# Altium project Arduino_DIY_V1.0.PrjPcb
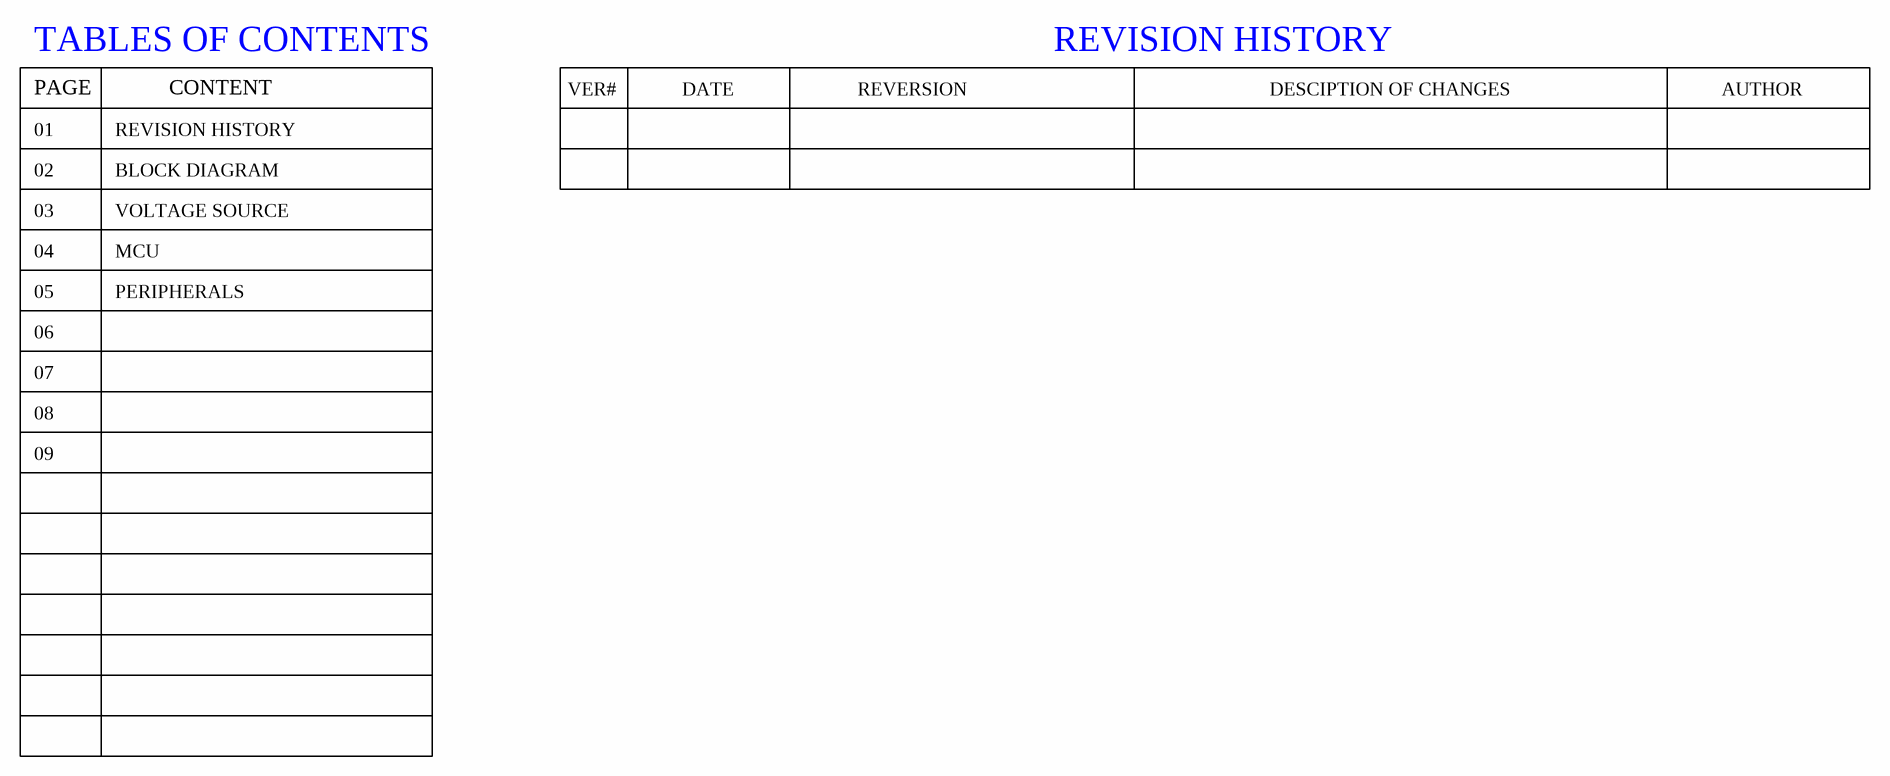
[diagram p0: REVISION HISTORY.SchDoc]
5 sheets, 121 parts. Net scope: flat (ports and power ports of the same name join across sheets).
Board file: Arduino_DIY_V1.0.PcbDoc
Sheets:
  REVISION HISTORY.SchDoc
  BLOCK DIAGRAM.SchDoc
  VOLTAGE SOURCE.SchDoc
  MCU.SchDoc
  Peripheral.SchDoc

## Sheet REVISION HISTORY.SchDoc: REVISION HISTORY
size A3; Author: NGUYEN QUANG MINH; SheetNumber: 1; SheetTotal: 5; ProjectTitle: Arduino_DIY_V1.0

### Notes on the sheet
- TABLES OF CONTENTS
- PAGE
- CONTENT
- VER#
- DATE
- REVERSION
- REVISION HISTORY
- DESCIPTION OF CHANGES
- AUTHOR
- 01
- 02
- 03
- BLOCK DIAGRAM
- VOLTAGE SOURCE
- 04
- MCU
- 05
- 06
- PERIPHERALS
- 07
- 08
- 09

## Sheet BLOCK DIAGRAM.SchDoc: BLOCK DIAGRAM
size A3; Author: NGUYEN QUANG MINH; SheetNumber: 2; SheetTotal: 5; ProjectTitle: Arduino_DIY_V1.0
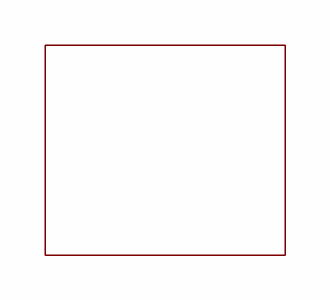
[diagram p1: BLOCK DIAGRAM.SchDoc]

## Sheet VOLTAGE SOURCE.SchDoc: VOLTAGE SOURCE
size A3; Author: NGUUYEN QUANG MINH; Organization: My Company; Address1: Address Line 1; Address2: Address Line 2; Address3: Address Line 3; Address4: Address Line 4; SheetNumber: 3; SheetTotal: 5; ProjectTitle: Arduino_DIY_V1.0
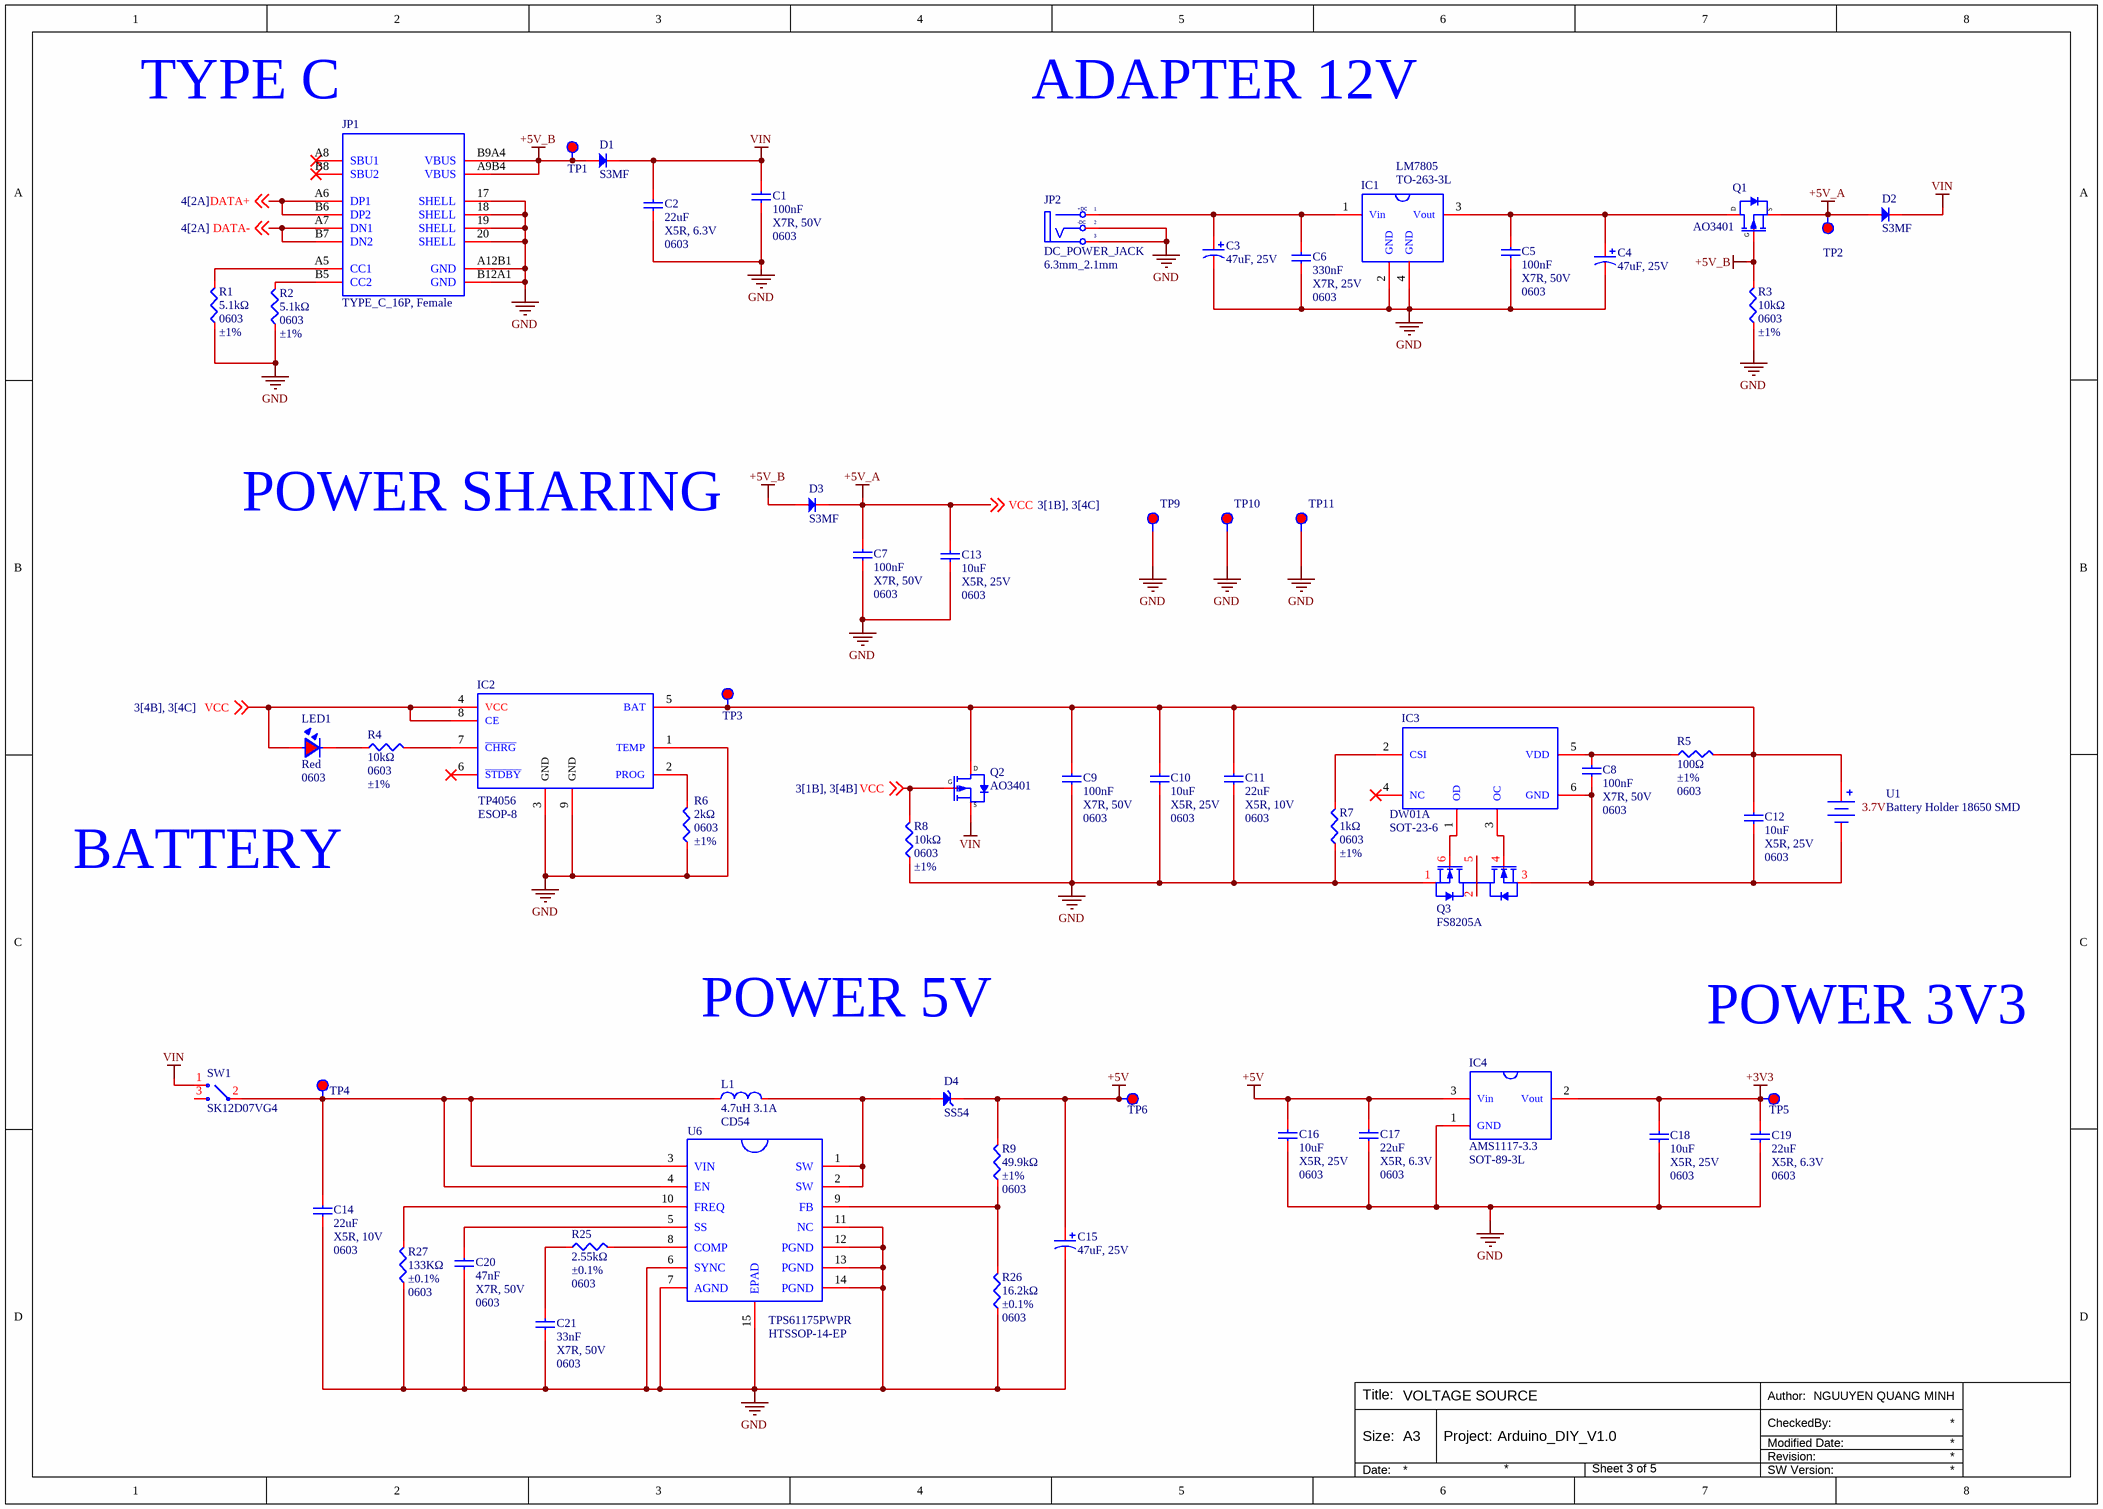
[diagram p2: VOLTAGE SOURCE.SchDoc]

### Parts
C1  100nF  Temperature Coefficient: X7R, 50V  Package: 0603  [C0603]
C2  22uF  Temperature Coefficient: X5R, 6.3V  Package: 0603  [C0603]
C3  47uF, 25V  [CAP_ALU_C]
C4  47uF, 25V  [CAP_ALU_C]
C5  100nF  Temperature Coefficient: X7R, 50V  Package: 0603  [C0603]
C6  330nF  Temperature Coefficient: X7R, 25V  Package: 0603  [C0603]
C7  100nF  Temperature Coefficient: X7R, 50V  Package: 0603  [C0603]
C8  100nF  Temperature Coefficient: X7R, 50V  Package: 0603  [C0603]
C9  100nF  Temperature Coefficient: X7R, 50V  Package: 0603  [C0603]
C10  10uF  Temperature Coefficient: X5R, 25V  Package: 0603  [C0603]
C11  22uF  Temperature Coefficient: X5R, 10V  Package: 0603  [C0603]
C12  10uF  Temperature Coefficient: X5R, 25V  Package: 0603  [C0603]
C13  10uF  Temperature Coefficient: X5R, 25V  Package: 0603  [C0603]
C14  22uF  Temperature Coefficient: X5R, 10V  Package: 0603  [C0603]
C15  47uF, 25V  [CAP_ALU_C]
C16  10uF  Temperature Coefficient: X5R, 25V  Package: 0603  [C0603]
C17  22uF  Temperature Coefficient: X5R, 6.3V  Package: 0603  [C0603]
C18  10uF  Temperature Coefficient: X5R, 25V  Package: 0603  [C0603]
C19  22uF  Temperature Coefficient: X5R, 6.3V  Package: 0603  [C0603]
C20  47nF  Temperature Coefficient: X7R, 50V  Package: 0603  [C0603]
C21  33nF  Temperature Coefficient: X7R, 50V  Package: 0603  [C0603]
D1  S3MF  [D_SMAF_L3.5-W2.6-LS4.7-RD]
D2  S3MF  [D_SMAF_L3.5-W2.6-LS4.7-RD]
D3  S3MF  [D_SMAF_L3.5-W2.6-LS4.7-RD]
D4  SS54  [SMC]
IC1  LM7805  [TO-263-3L]
IC2  TP4056  [ESOP-8]
IC3  DW01A  [SOT-23-6]
IC4  AMS1117-3.3  [SOT-89-3L]
JP1  TYPE_C_16P, Female  [TYPE_C_16P]
JP2  DC_POWER_JACK  Reference: 6.3mm_2.1mm  [DC_POWER_JACK_6.3mm_2.1mm]
L1  4.7uH 3.1A  [CD54]
LED1  Red  Package: 0603  [LED0603_RED]
Q1  AO3401  [TF_SOT_23_3]
Q2  AO3401  [TF_SOT_23_3]
Q3  FS8205A  [TF_SOT23-6]
R1  5.1kΩ  Package: 0603  Tolerance: ±1%  [R0603]
R2  5.1kΩ  Package: 0603  Tolerance: ±1%  [R0603]
R3  10kΩ  Package: 0603  Tolerance: ±1%  [R0603]
R4  10kΩ  Package: 0603  Tolerance: ±1%  [R0603]
R5  100Ω  Tolerance: ±1%  Package: 0603  [R0603]
R6  2kΩ  Package: 0603  Tolerance: ±1%  [R0603]
R7  1kΩ  Package: 0603  Tolerance: ±1%  [R0603]
R8  10kΩ  Package: 0603  Tolerance: ±1%  [R0603]
R9  49.9kΩ  Tolerance: ±1%  Package: 0603  [R0603]
R25  2.55kΩ  Tolerance: ±0.1%  Package: 0603  [R0603]
R26  16.2kΩ  Tolerance: ±0.1%  Package: 0603  [R0603]
R27  133KΩ  Tolerance: ±0.1%  Package: 0603  [R0603]
SW1  SK12D07VG4  [SK12D07VG4]
TP1  Test Point  [TEST_POINT]  (value not drawn)  (no BOM)
TP2  Test Point  [TEST_POINT]  (value not drawn)  (no BOM)
TP3  Test Point  [TEST_POINT]  (value not drawn)  (no BOM)
TP4  Test Point  [TEST_POINT]  (value not drawn)  (no BOM)
TP5  Test Point  [TEST_POINT]  (value not drawn)  (no BOM)
TP6  Test Point  [TEST_POINT]  (value not drawn)  (no BOM)
TP9  Test Point  [TEST_POINT]  (value not drawn)  (no BOM)
TP10  Test Point  [TEST_POINT]  (value not drawn)  (no BOM)
TP11  Test Point  [TEST_POINT]  (value not drawn)  (no BOM)
U1  Battery Holder 18650 SMD  [PIN_18650_1S_HOLDER_SMD]
U6  TPS61175PWPR  [HTSSOP-14-EP]

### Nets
+3V3: C18.2 C19.2 IC4.2(Vout) TP5.1
+5V: C15.1 C16.2 C17.2 D4.1 IC4.3(Vin) R9.2 TP6.1
+5V_A: C7.2 C13.2 D2.2 D3.1 IC2.4(VCC) IC2.8(CE) LED1.1 Q1.2(S) Q2.1(G) R8.2 TP2.1 ; off-sheet VCC  [also labelled VCC]
+5V_B: D1.2 D3.2 JP1.A9B4(VBUS) JP1.B9A4(VBUS) Q1.1(G) R3.2 TP1.1
GND: C1.1 C2.1 C3.2 C4.2 C5.1 C6.1 C7.1 C9.1 C10.1 C11.1 C13.1 C14.1 C15.2 C16.1 C17.1 C18.1 C19.1 C20.1 C21.1 IC1.2(GND) IC1.4(GND) IC2.1(TEMP) IC2.3(GND) IC2.9(GND) IC4.1(GND) JP1.17(SHELL) JP1.18(SHELL) JP1.19(SHELL) JP1.20(SHELL) JP1.A12B1(GND) JP1.B12A1(GND) JP2.2(TN) JP2.3(S) Q3.1(S1) R1.1 R2.1 R3.1 R6.1 R7.1 R8.1 R26.1 R27.1 TP9.1 TP10.1 TP11.1 U6.6(SYNC) U6.7(AGND) U6.11(NC) U6.12(PGND) U6.13(PGND) U6.14(PGND) U6.15(EPAD)
VIN: C1.2 C2.2 D1.1 D2.1 Q2.2(S) SW1.1
DATA+: JP1.A6(DP1) JP1.B6(DP2) ; off-sheet DATA+
DATA-: JP1.A7(DN1) JP1.B7(DN2) ; off-sheet DATA-
NetC3_1: C3.1 C6.2 IC1.1(Vin) JP2.1(T)
NetC4_1: C4.1 C5.2 IC1.3(Vout) Q1.3(D)
NetC8_1: C8.1 C12.1 IC3.6(GND) Q3.3(S2) U1.2
NetC8_2: C8.2 IC3.5(VDD) R5.1
NetC9_2: C9.2 C10.2 C11.2 C12.2 IC2.5(BAT) Q2.3(D) R5.2 TP3.1 U1.1
NetC14_2: C14.2 L1.1 SW1.2 TP4.1 U6.3(VIN) U6.4(EN)
NetC20_2: C20.2 U6.5(SS)
NetC21_2: C21.2 R25.1
NetD4_2: D4.2 L1.2 U6.1(SW) U6.2(SW)
NetIC2_2: IC2.2(PROG) R6.2
NetIC2_7: IC2.7(~{CHRG}) R4.2
NetIC3_1: IC3.1(OD) Q3.6(G1)
NetIC3_2: IC3.2(CSI) R7.2
NetIC3_3: IC3.3(OC) Q3.4(G2)
NetJP1_A5: JP1.A5(CC1) R1.2
NetJP1_B5: JP1.B5(CC2) R2.2
NetLED1_2: LED1.2 R4.1
NetQ3_2: Q3.2(D1/D2) Q3.5(D1/D2)
NetR9_1: R9.1 R26.2 U6.9(FB)
NetR25_2: R25.2 U6.8(COMP)
NetR27_2: R27.2 U6.10(FREQ)

Not connected (* = marked no-connect by the designer): IC2 6(~{STDBY})*; IC3 4(NC)*; JP1 A8(SBU1)* B8(SBU2)*; SW1 3

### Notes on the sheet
- TYPE C
- ADAPTER 12V
- POWER SHARING
- BATTERY
- POWER 5V
- POWER 3V3

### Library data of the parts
C1 C5 C7-C9 = C0603_MLCC_100nF_X7R_50V: 50V 100nF X7R ±10% 0603 Multilayer Ceramic Capacitors MLCC - SMD/SMT ROHS; Manufacturer: YAGEO; Mfr. Part: CC0603KRX7R9BB104
C2 C17 C19 = C0603_MLCC_22uF_X5R_6.3V: 6.3V 22uF X5R ±20% 0603 Multilayer Ceramic Capacitors MLCC - SMD/SMT ROHS; Manufacturer: YAGEO; Mfr. Part: CC0603MRX5R5BB226
C3 C4 C15 = C_ALU_47uF_25V_C: 25V ±20% 47uF SMD,D5xL6.1mm Hybrid Aluminum Electrolytic Capacitors ROHS; Manufacturer: PANASONIC; Mfr. Part: EEHZK1E470R
C6 = C0603_MLCC_330nF_X7R_25V: 25V 330nF X7R ±10% 0603 Multilayer Ceramic Capacitors MLCC - SMD/SMT ROHS; Manufacturer: YAGEO; Mfr. Part: CC0603KRX7R8BB334
C10 C12 C13 C16 C18 = C0603_MLCC_10uF_X5R_25V: 25V 10uF X5R ±20% 0603 Multilayer Ceramic Capacitors MLCC - SMD/SMT ROHS; Manufacturer: YAGEO; Mfr. Part: CC0603MRX5R8BB106
C11 C14 = C0603_MLCC_22uF_X5R_10V: 10V 22uF X5R ±20% 0603 Multilayer Ceramic Capacitors MLCC - SMD/SMT ROHS; Manufacturer: Samsung Electro-Mechanics; Mfr. Part: CL10A226MP8NUNE
C20 = C0603_MLCC_47nF_X7R_50V: 50V 47nF X7R ±10% 0603 Multilayer Ceramic Capacitors MLCC - SMD/SMT ROHS; Manufacturer: YAGEO; Mfr. Part: CC0603KRX7R9BB473
C21 = C0603_MLCC_33nF_X7R_50V: 50V 33nF X7R ±10% 0603 Multilayer Ceramic Capacitors MLCC - SMD/SMT ROHS; Manufacturer: YAGEO; Mfr. Part: CC0603KRX7R9BB333
D1-D3 = S3MF: 3A Independent Type 1.1V@3A 1kV SMAF Diodes - General Purpose ROHS; Manufacturer: Shandong Jingdao Microelectronics
D4 = SS54: 40V Independent 550mV@5A 5A SMC Schottky Diodes ROHS; Manufacturer: TWGMC
IC1 = LM7805_TO-263-3L: 62dB@(120Hz) 1A Fixed 4.8V~5.2V Positive 35V TO-263-3L Voltage Regulators - Linear, Low Drop Out (LDO) Regulators ROHS; Manufacturer: HANSCHIP semiconductor; Mfr. Part: LM7805SRG; Number of Outputs: 1
IC2 = TP4056_ESOP-8: 4V~6V Lithium-ion/Polymer 1 ESOP-8 Battery Management ROHS; Manufacturer: TPOWER; Key Attributes: 1A Lithium Battery Charger; Number of Cells: 1; Charging Saturation Voltage: 4.2V
IC3 = DW01A: 1.5V~8V Lithium-ion/Polymer 1 SOT-23-6 Battery Management ROHS; Manufacturer: YONGYUTAI; Key Attributes: Lithium battery protection circuit; Number of Cells: 1; Charging Saturation Voltage: 4.3V
IC4 = AMS1117-3.3_SOT-89-3L: 1A Fixed 3.3V Positive 15V SOT-89-3L Voltage Regulators - Linear, Low Drop Out (LDO) Regulators ROHS; Manufacturer: HXY MOSFET; Voltage Dropout: 12mV@(1A); Number of Outputs: 1; Voltage - Supply: 16V
JP1 = TYPE_C_16P: 3A USB 3.1 1 Surface Mount, Right Angle 16P Female -40℃~+85℃ Type-C SMD USB Connectors ROHS; Manufacturer: SHOU HAN; Mfr. Part: TYPE-C-3.1-16PIN; Protocol Standard: USB 3.1
JP2 = DC_POWER_JACK_6.3mm_2.1mm: Right Angle DC Power Jack -40℃~+85℃ 2.1mm 6.3mm 3A 500V Through Hole DC Power Connectors ROHS; Manufacturer: Lian Xin Technology; Mfr. Part: XDJK-0051-025
L1 = CD54_4.7uH_3.1A: 3.1A 4.7uH ±20% SMD,5.8x5.2mm Power Inductors ROHS; Manufacturer: Ceaiya; Manufacture Part Number: CD54-4R7M
LED1 = LED0603_Red: 20mA 230mcd Water Clear -40℃~+85℃ 630nm Red 120° 75mW 1.95V 0603 LED Indication - Discrete ROHS; Manufacturer: Kingbright; Mfr. Part: APT1608SURCK; Key Attributes: 1.6 x 0.8 mm SMD Chip LED Lamp
Q1 Q2 = AO3401: 30V 4.2A 42mΩ@10V,4A 1.4W 800mV@250uA 1 Piece P-Channel SOT-23 MOSFETs ROHS; Manufacturer: ElecSuper
Q3 = FS8205A: 20V 25mΩ@2.5V,3A 1.5W 500mV SOT-23-6 MOSFETs ROHS; Manufacturer: TECH PUBLIC
R1 R2 = R0603_5.1kΩ_±1%: 100mW Thick Film Resistor 75V ±100ppm/℃ ±1% 5.1kΩ 0603 Chip Resistor - Surface Mount ROHS; Manufacturer: YAGEO; Mfr. Part: RC0603FR-075K1L
R3 R4 R8 = R0603_10kΩ_±1%: 100mW Thick Film Resistor 75V ±100ppm/℃ ±1% 10kΩ 0603 Chip Resistor - Surface Mount ROHS; Manufacturer: YAGEO; Mfr. Part: RC0603FR-0710KL
R5 = R0603_100Ω_±1%: 100mW Thick Film Resistor 75V ±100ppm/℃ ±1% 100Ω 0603 Chip Resistor - Surface Mount ROHS; Manufacturer: YAGEO; Mfr. Part: RC0603FR-13100RL
R6 = R0603_2kΩ_±1%: 100mW Thick Film Resistor 75V ±100ppm/℃ ±1% 2kΩ 0603 Chip Resistor - Surface Mount ROHS; Manufacturer: YAGEO; Mfr. Part: RC0603FR-072KL
R7 = R0603_1kΩ_±1%: 100mW Thick Film Resistor 75V ±100ppm/℃ ±1% 1kΩ 0603 Chip Resistor - Surface Mount ROHS; Manufacturer: YAGEO; Mfr. Part: RC0603FR-071KL
R9 = R0603_49.9KΩ_±1%: 100mW Thick Film Resistor 75V ±100ppm/℃ ±1% 49.9kΩ 0603 Chip Resistor - Surface Mount ROHS; Manufacturer: YAGEO; Mfr. Part: RC0603FR-0749K9L
R25 = R0603_2.55KΩ_±0.1%: 100mW Thin Film Resistor 75V ±25ppm/℃ ±0.1% 2.55kΩ 0603 Chip Resistor - Surface Mount ROHS; Manufacturer: YAGEO; Mfr. Part: RT0603BRD072K55L
R26 = R0603_16.2KΩ_±0.1%: 100mW Thin Film Resistor 75V ±50ppm/℃ ±0.1% 16.2kΩ 0603 Chip Resistor - Surface Mount ROHS; Manufacturer: YAGEO; Mfr. Part: RT0603BRE0716K2L
R27 = R0603_133KΩ_±0.1%: 100mW Thin Film Resistor 75V ±50ppm/℃ ±0.1% 133kΩ 0603 Chip Resistor - Surface Mount ROHS; Manufacturer: YAGEO; Mfr. Part: RT0603BRE07133KL
SW1 = SK12D07VG4: 500mA SPDT 50V 5千次 Plugin Slide Switches ROHS; Manufacturer: SHOU HAN
TP1-TP6 TP9-TP11 = TEST_POINT
U1 = PIN_18650_1S_HOLDER_SMD: Battery Holder -10℃~+100℃ Gold Phosphor Bronze Button And Strip Battery Connector ROHS; Manufacturer: MYOUNG; Mfr. Part: BH-18650-B5BA008; Battery Type: 18650
U6 = TPS61175PWPR: Boost Adjustable 2.9V~38V 2.9V~18V 3A HTSSOP-14-EP DC-DC Converters ROHS; Manufacturer: TI; Frequency - Switching: 2.2MHz; Number of Outputs: 1

## Sheet MCU.SchDoc: MCU
size A3; Author: NGUYEN QUANG MINH; SheetNumber: 4; SheetTotal: 5; ProjectTitle: Arduino_DIY_V1.0
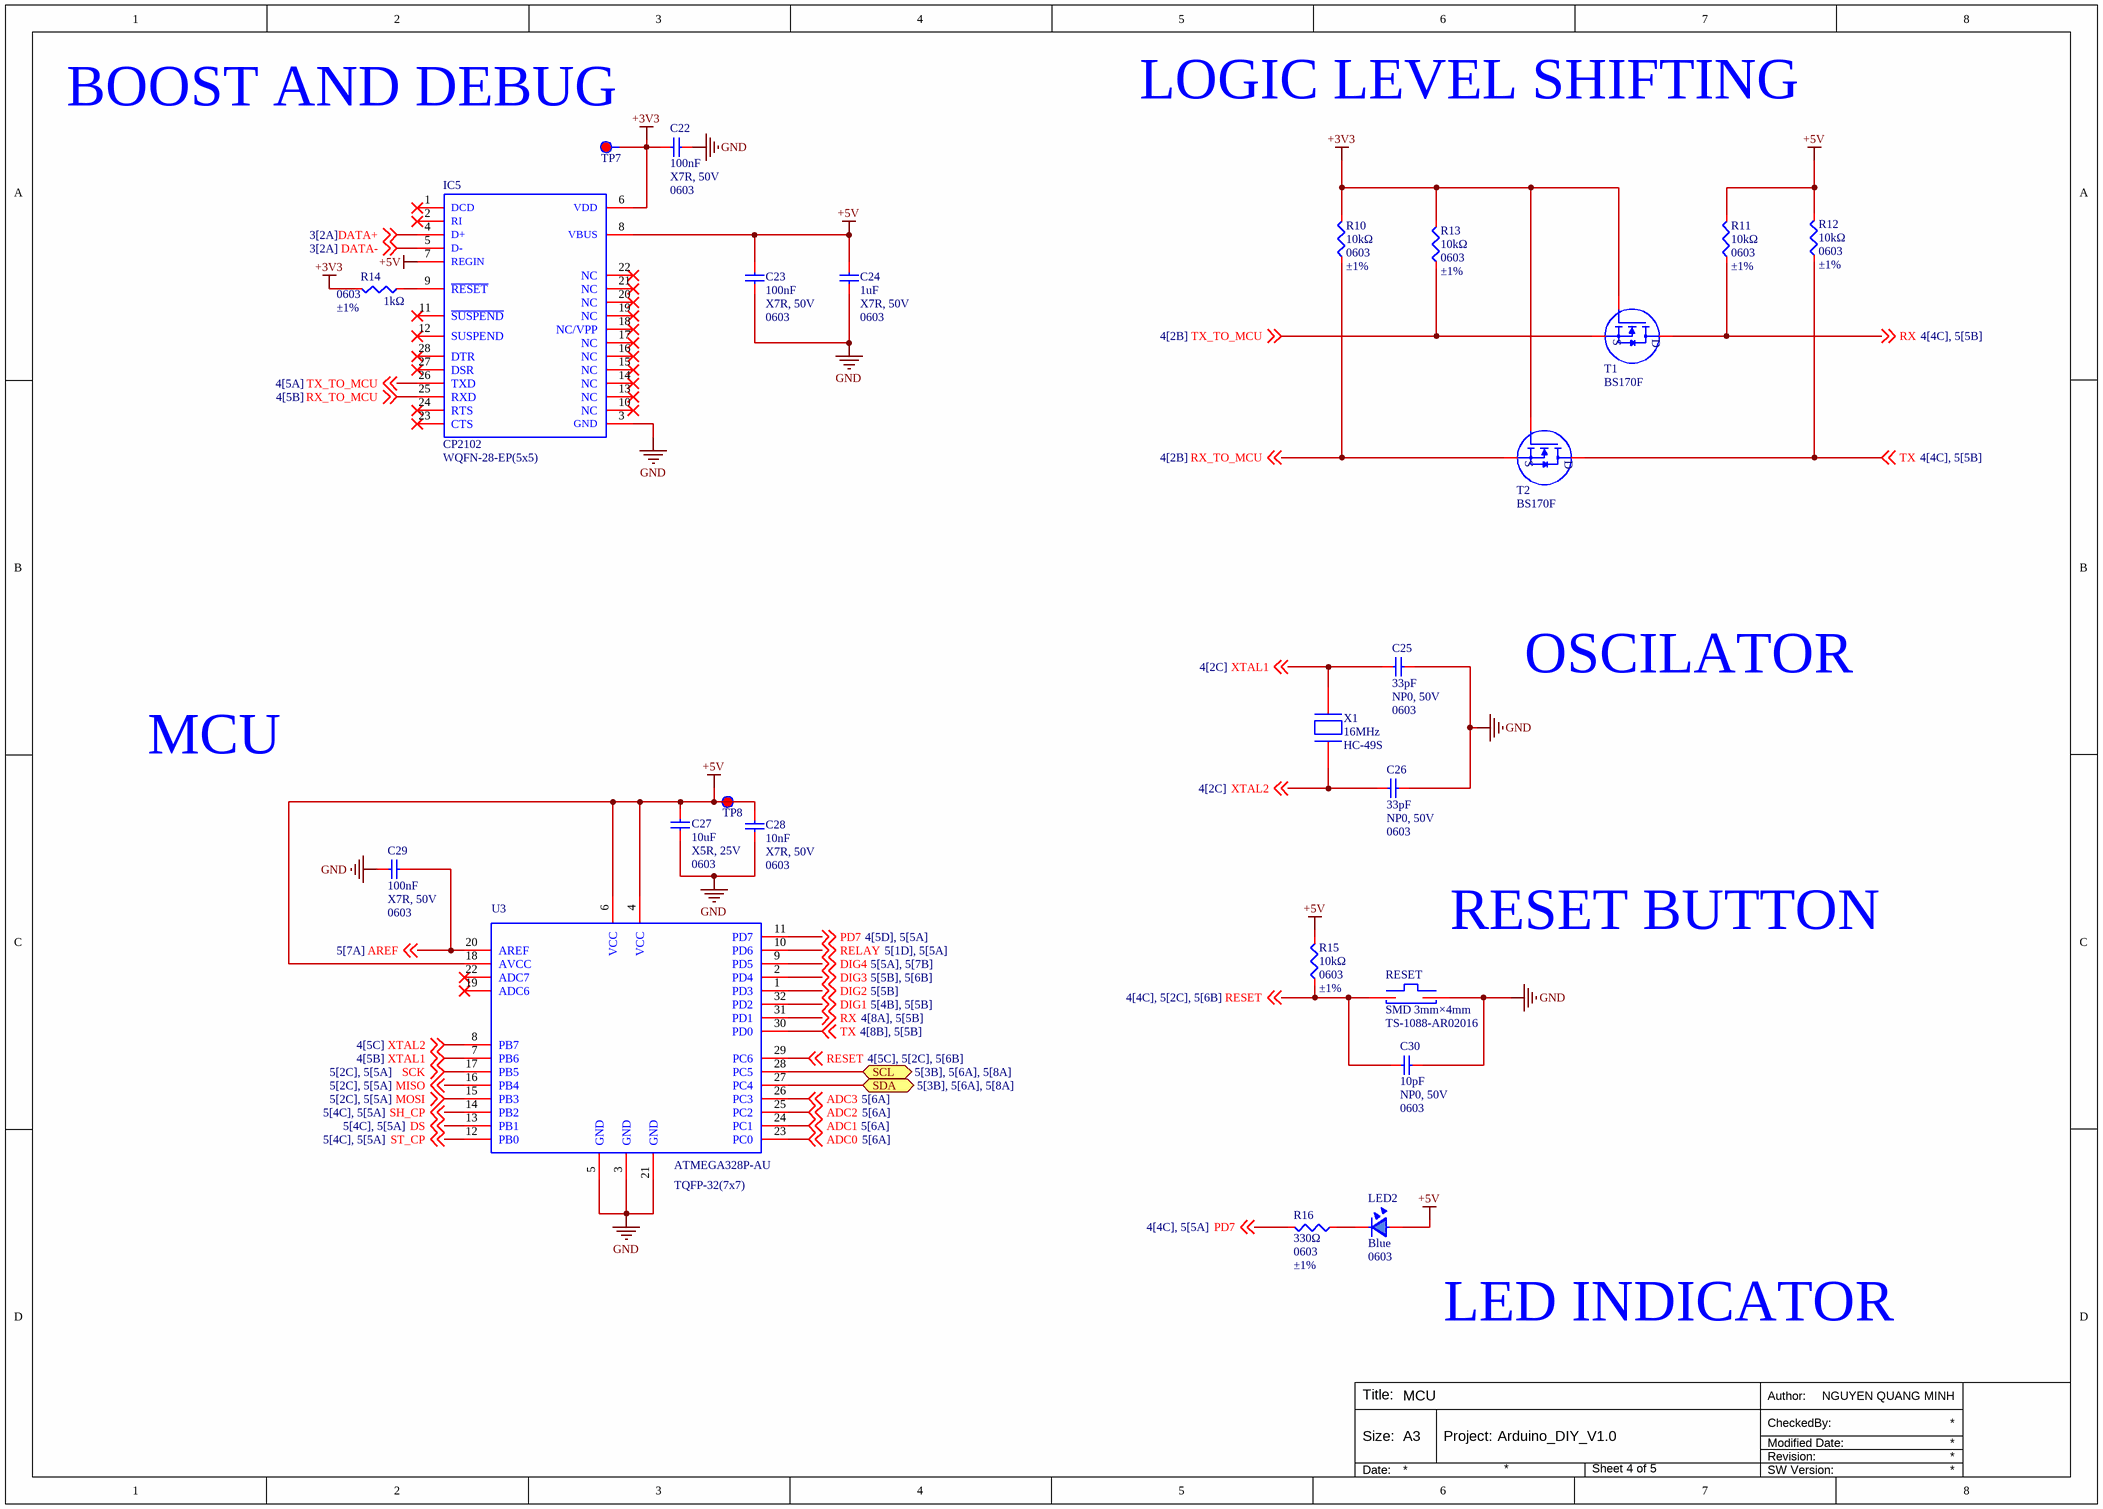
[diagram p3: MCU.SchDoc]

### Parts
C22  100nF  Temperature Coefficient: X7R, 50V  Package: 0603  [C0603]
C23  100nF  Temperature Coefficient: X7R, 50V  Package: 0603  [C0603]
C24  1uF  Temperature Coefficient: X7R, 50V  Package: 0603  [C0603]
C25  33pF  Temperature Coefficient: NP0, 50V  Package: 0603  [C0603]
C26  33pF  Temperature Coefficient: NP0, 50V  Package: 0603  [C0603]
C27  10uF  Temperature Coefficient: X5R, 25V  Package: 0603  [C0603]
C28  10nF  Temperature Coefficient: X7R, 50V  Package: 0603  [C0603]
C29  100nF  Temperature Coefficient: X7R, 50V  Package: 0603  [C0603]
C30  10pF  Temperature Coefficient: NP0, 50V  Package: 0603  [C0603]
IC5  CP2102  [WQFN-28-EP(5x5)]
LED2  Blue  Package: 0603  [LED0603_BLUE]
R10  10kΩ  Package: 0603  Tolerance: ±1%  [R0603]
R11  10kΩ  Package: 0603  Tolerance: ±1%  [R0603]
R12  10kΩ  Package: 0603  Tolerance: ±1%  [R0603]
R13  10kΩ  Package: 0603  Tolerance: ±1%  [R0603]
R14  1kΩ  Package: 0603  Tolerance: ±1%  [R0603]
R15  10kΩ  Package: 0603  Tolerance: ±1%  [R0603]
R16  330Ω  Package: 0603  Tolerance: ±1%  [R0603]
RESET  SMD 3mm×4mm  Mfr. Part: TS-1088-AR02016  [ROUND_BUTTON_SMD 3*4mm]
T1  BS170F  [SOT-23]
T2  BS170F  [SOT-23]
TP7  Test Point  [TEST_POINT]  (value not drawn)  (no BOM)
TP8  Test Point  [TEST_POINT]  (value not drawn)  (no BOM)
U3  ATMEGA328P-AU  Package: TQFP-32(7x7)  [TQFP-32 (7x7)]
X1  16MHz  [HC-49S]

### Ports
SCL (bidir, see 5[3B], 5[6A], 5[8A]), SDA (bidir, see 5[3B], 5[6A], 5[8A])

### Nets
+3V3: C22.2 IC5.6(VDD) R10.2 R13.2 R14.2 T1.1(G) T2.1(G) TP7.1
+5V: C23.2 C24.2 C27.2 C28.2 IC5.7(REGIN) IC5.8(VBUS) LED2.1 R11.2 R12.2 R15.2 TP8.1 U3.4(VCC) U3.6(VCC) U3.18(AVCC)
GND: C22.1 C23.1 C24.1 C25.2 C26.2 C27.1 C28.1 C29.1 C30.2 IC5.3(GND) RESET.2 U3.3(GND) U3.5(GND) U3.21(GND)
ADC0: U3.23(PC0) ; off-sheet ADC0
ADC1: U3.24(PC1) ; off-sheet ADC1
ADC2: U3.25(PC2) ; off-sheet ADC2
ADC3: U3.26(PC3) ; off-sheet ADC3
AREF: C29.2 U3.20(AREF) ; off-sheet AREF
DATA+: IC5.4(D+) ; off-sheet DATA+
DATA-: IC5.5(D-) ; off-sheet DATA-
DIG1: U3.32(PD2) ; off-sheet DIG1
DIG2: U3.1(PD3) ; off-sheet DIG2
DIG3: U3.2(PD4) ; off-sheet DIG3
DIG4: U3.9(PD5) ; off-sheet DIG4
DS: U3.13(PB1) ; off-sheet DS
MISO: U3.16(PB4) ; off-sheet MISO
MOSI: U3.15(PB3) ; off-sheet MOSI
PD7: R16.1 U3.11(PD7) ; off-sheet PD7
RELAY: U3.10(PD6) ; off-sheet RELAY
RESET: C30.1 R15.1 RESET.1 U3.29(PC6) ; off-sheet RESET
RX: R11.1 T1.3(D) U3.31(PD1) ; off-sheet RX
RX_TO_MCU: IC5.25(RXD) R10.1 T2.2(S) ; off-sheet RX_TO_MCU
SCK: U3.17(PB5) ; off-sheet SCK
SH_CP: U3.14(PB2) ; off-sheet SH_CP
ST_CP: U3.12(PB0) ; off-sheet ST_CP
TX: R12.1 T2.3(D) U3.30(PD0) ; off-sheet TX
TX_TO_MCU: IC5.26(TXD) R13.1 T1.2(S) ; off-sheet TX_TO_MCU
XTAL1: C25.1 U3.7(PB6) X1.2 ; off-sheet XTAL1
XTAL2: C26.1 U3.8(PB7) X1.1 ; off-sheet XTAL2
NetH2_1: U3.28(PC5) ; port SCL
NetH2_2: U3.27(PC4) ; port SDA
NetIC5_9: IC5.9(~{RESET}) R14.1
NetLED2_2: LED2.2 R16.2

Not connected (* = marked no-connect by the designer): IC5 1(DCD)* 2(RI)* 10(NC)* 11(~{SUSPEND})* 12(SUSPEND)* 13(NC)* 14(NC)* 15(NC)* 16(NC)* 17(NC)* 18(NC/VPP)* 19(NC)* 20(NC)* 21(NC)* 22(NC)* 23(CTS)* 24(RTS)* 27(DSR)* 28(DTR)*; U3 19(ADC6)* 22(ADC7)*

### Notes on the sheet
- LOGIC LEVEL SHIFTING
- BOOST AND DEBUG
- OSCILATOR
- MCU
- RESET BUTTON
- LED INDICATOR

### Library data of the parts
C22 C23 C29 = C0603_MLCC_100nF_X7R_50V: as C1 on sheet VOLTAGE SOURCE
C24 = C0603_MLCC_1uF_X7R_50V: 50V 1uF X7R ±10% 0603 Multilayer Ceramic Capacitors MLCC - SMD/SMT ROHS; Manufacturer: YAGEO; Mfr. Part: CC0603KRX7R9BB105
C25 C26 = C0603_MLCC_33pF_NP0_50V: 50V 33pF NP0 ±5% 0603 Multilayer Ceramic Capacitors MLCC - SMD/SMT ROHS; Manufacturer: YAGEO; Mfr. Part: CC0603JRNPO9BN330
C27 = C0603_MLCC_10uF_X5R_25V: as C10 on sheet VOLTAGE SOURCE
C28 = C0603_MLCC_10nF_X7R_50V: 50V 10nF X7R ±10% 0603 Multilayer Ceramic Capacitors MLCC - SMD/SMT ROHS; Manufacturer: YAGEO; Mfr. Part: CC0603KRX7R9BB103
C30 = C0603_MLCC_10pF_NP0_50V: 50V 10pF NP0 ±5% 0603 Multilayer Ceramic Capacitors MLCC - SMD/SMT ROHS; Manufacturer: YAGEO; Mfr. Part: CC0603JRNPO9BN100
IC5 = CP2102: 12Mbps Transceiver WQFN-28-EP(5x5) USB Converters ROHS; Manufacturer: SILICON LABS; Mfr. Part: CP2102-GMR; Key Attributes: Single-Chip USB to UART Bridge; Voltage - Supply: 3V~3.6V
LED2 = LED0603_Blue: 2mA 24mcd Water Clear -40℃~+85℃ 470nm Blue 130° 120mW 2.65V 0603 LED Indication - Discrete ROHS; Manufacturer: Kingbright; Mfr. Part: APT1608LVBC/D; Key Attributes: 1.6 x 0.8 mm SMD Chip LED Lamp
R10-R13 R15 = R0603_10kΩ_±1%: as R3 on sheet VOLTAGE SOURCE
R14 = R0603_1kΩ_±1%: as R7 on sheet VOLTAGE SOURCE
R16 = R0603_330Ω_±1%: 100mW Thick Film Resistor 75V ±100ppm/℃ ±1% 330Ω 0603 Chip Resistor - Surface Mount ROHS; Manufacturer: YAGEO; Mfr. Part: RC0603FR-07330RL
RESET = SW_BUTTON_SMD_3mm×4mm: Without Bracket 50mA 4mm 100,000 Cycles 12V 1.6N 3mm 2mm Round Button Surface Mount,Vertical SPST SMD Tactile Switches ROHS; Manufacturer: XUNPU
T1 T2 = BS170F: 90V 150uA 5Ω@10V 330mW 3V@1mA 1 N-Channel SOT-23 MOSFETs ROHS; Manufacturer: DIODES
TP7 TP8 = TEST_POINT
U3 = ATMEGA328P-AU: AVR 20MHz TQFP-32(7x7) Microcontrollers (MCU/MPU/SOC) ROHS; Manufacturer: MICROCHIP; Key Attributes: 8-bit Microcontroller with In-System Programmable Flash; ADC (Bit): 10bit; Number of I/O: 23; Program Memory Type: FLASH; EEPROM: 1KB; Program Storage Size: 32KB; Voltage - Supply: 1.8V~5.5V
X1 = Crystal_16Mhz_HC49S: 16MHz Through Hole Crystal Oscillator 20pF ±20ppm ±30ppm HC-49S Crystals ROHS; Manufacturer: YXC Crystal Oscillators; Mfr. Part: X49SD16MSD2SC

## Sheet Peripheral.SchDoc
size A3; SheetNumber: 5; SheetTotal: 5
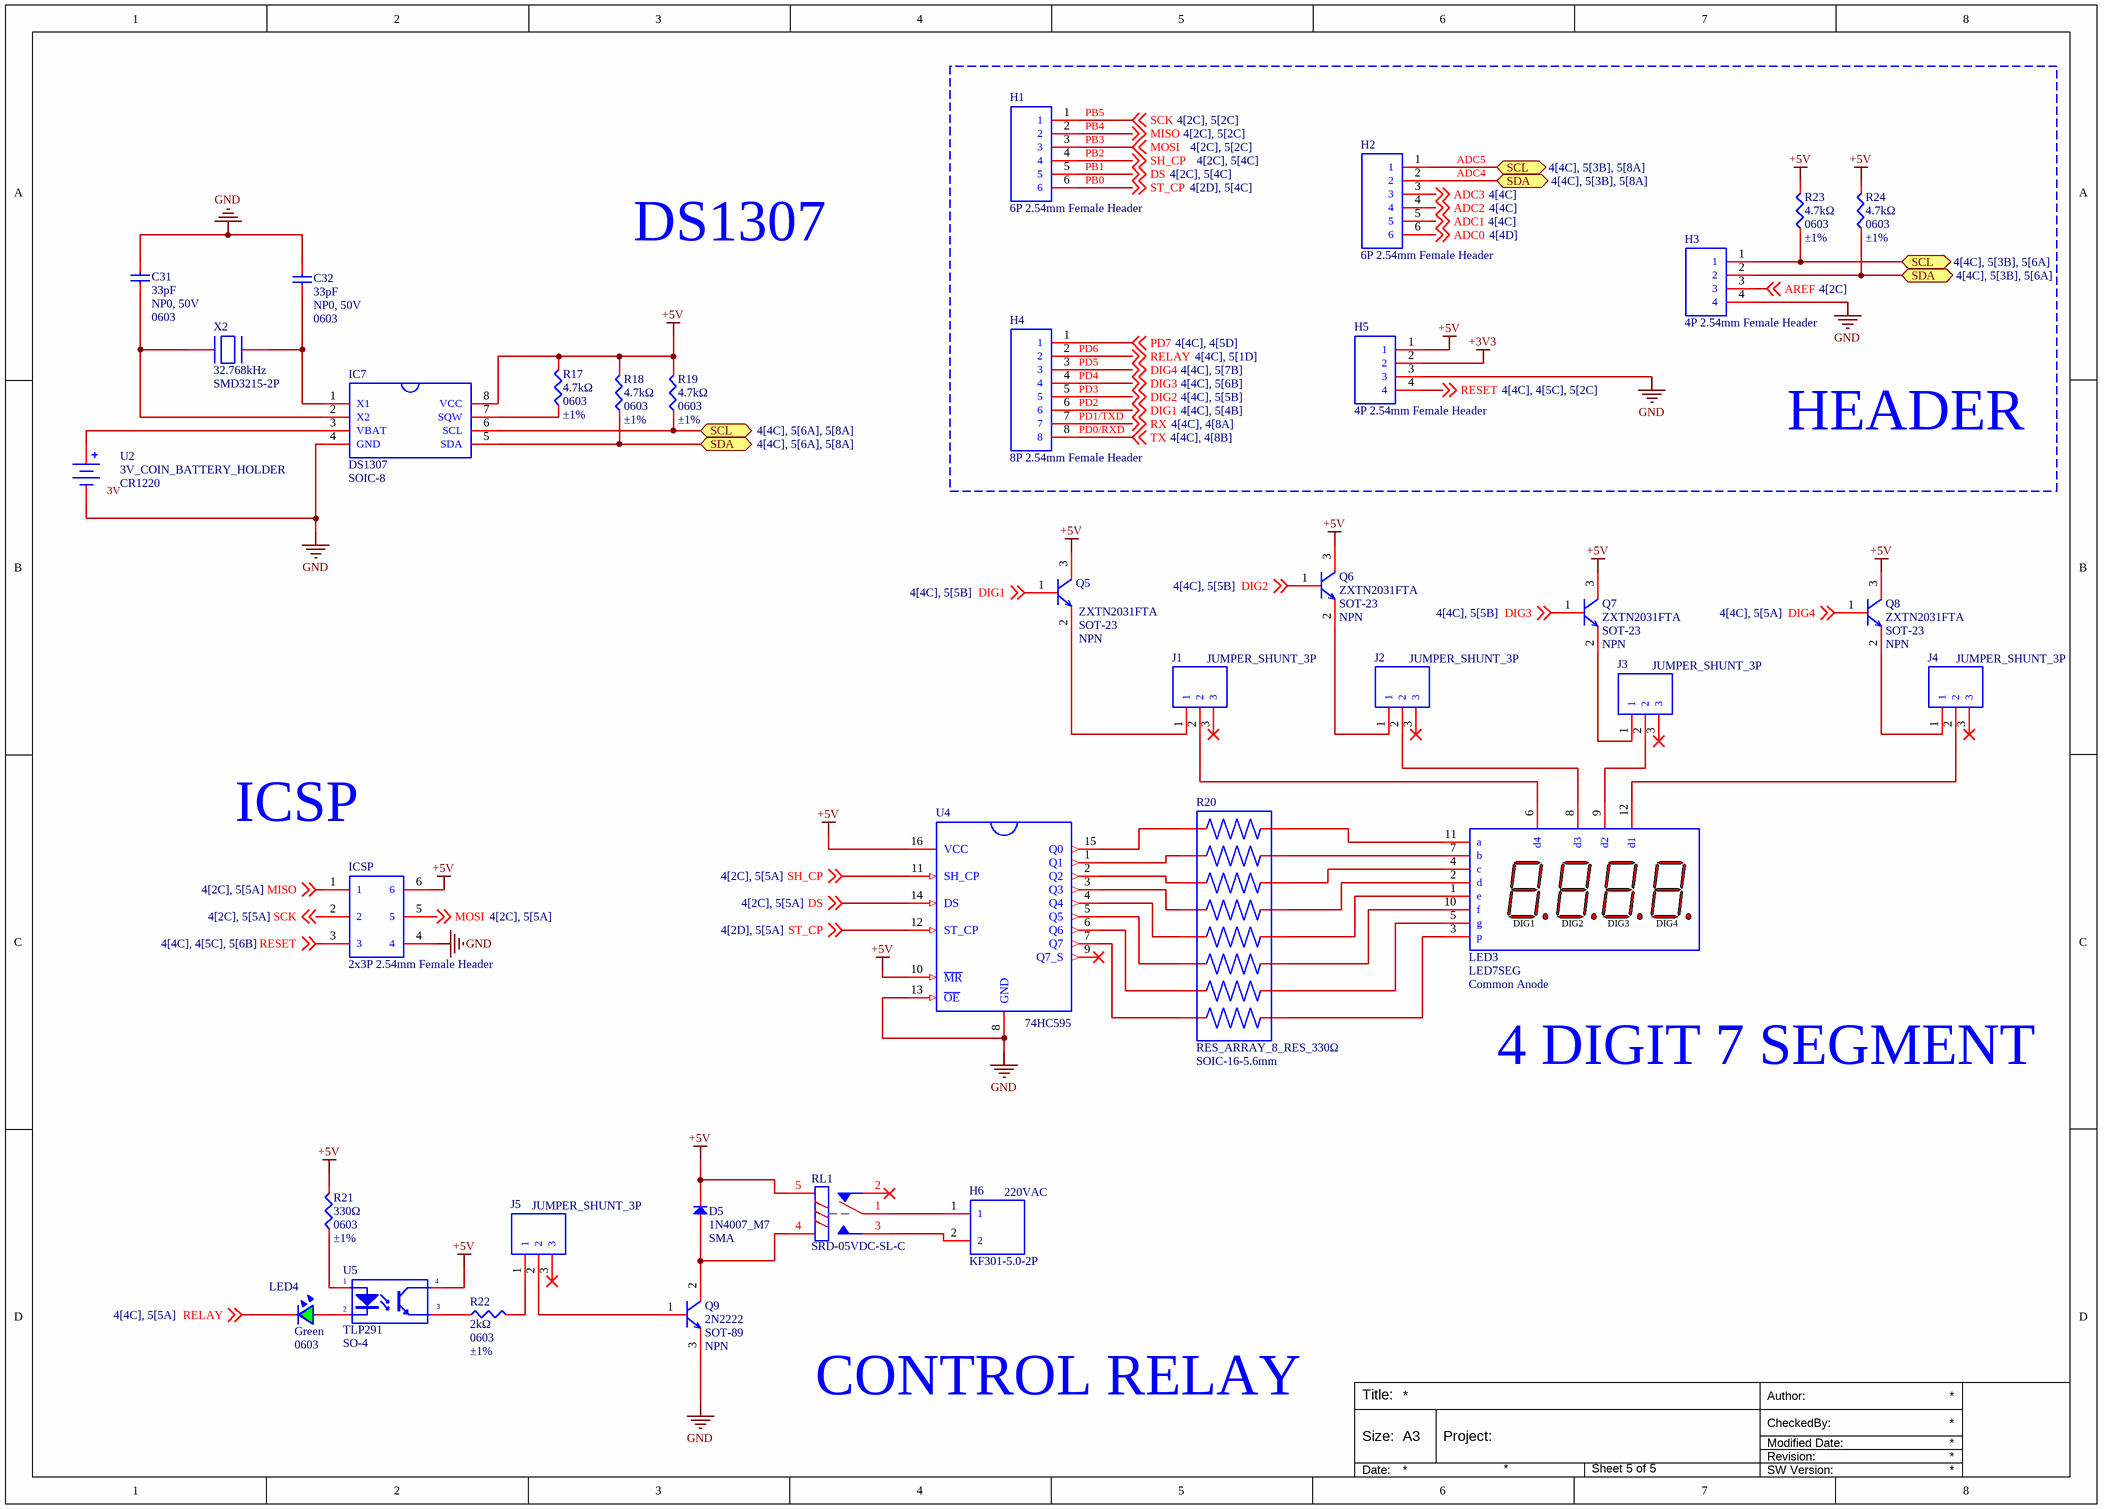
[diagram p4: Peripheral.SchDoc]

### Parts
C31  33pF  Temperature Coefficient: NP0, 50V  Package: 0603  [C0603]
C32  33pF  Temperature Coefficient: NP0, 50V  Package: 0603  [C0603]
D5  1N4007_M7  Package: SMA  [SMA(DO-214AC)]
H1  6P 2.54mm Female Header  [6P, 2,54mm, FEMALE HEADER]
H2  6P 2.54mm Female Header  [6P, 2,54mm, FEMALE HEADER]
H3  4P 2.54mm Female Header  [4P, 2,54mm, FEMALE HEADER]
H4  8P 2.54mm Female Header  [8P, 2,54mm, FEMALE HEADER]
H5  4P 2.54mm Female Header  [4P, 2,54mm, FEMALE HEADER]
H6  KF301-5.0-2P  CONFIGURE: 220VAC  [CONN-TH_P5.00_KF301-5.0-2P]
IC7  DS1307  [SOIC-8]
ICSP  2x3P 2.54mm Female Header  [2x3P, 2.54mm, Female Header]
J1  JUMPER_SHUNT_3P  [JUMPER_SHUNT_3P]
J2  JUMPER_SHUNT_3P  [JUMPER_SHUNT_3P]
J3  JUMPER_SHUNT_3P  [JUMPER_SHUNT_3P]
J4  JUMPER_SHUNT_3P  [JUMPER_SHUNT_3P]
J5  JUMPER_SHUNT_3P  [JUMPER_SHUNT_3P]
LED3  LED7SEG  LED Polarity: Common Anode  [LED7SEG_4]
LED4  Green  Package: 0603  [LED0603_GREEN]
Q5  ZXTN2031FTA  Type: NPN  [SOT-23]
Q6  ZXTN2031FTA  Type: NPN  [SOT-23]
Q7  ZXTN2031FTA  Type: NPN  [SOT-23]
Q8  ZXTN2031FTA  Type: NPN  [SOT-23]
Q9  2N2222  Package: SOT-89  Type: NPN  [SOT-89-3L]
R17  4.7kΩ  Package: 0603  Tolerance: ±1%  [R0603]
R18  4.7kΩ  Package: 0603  Tolerance: ±1%  [R0603]
R19  4.7kΩ  Package: 0603  Tolerance: ±1%  [R0603]
R20  RES_ARRAY_8_RES_330Ω  [SOIC-16-5.6mm]
R21  330Ω  Package: 0603  Tolerance: ±1%  [R0603]
R22  2kΩ  Package: 0603  Tolerance: ±1%  [R0603]
R23  4.7kΩ  Package: 0603  Tolerance: ±1%  [R0603]
R24  4.7kΩ  Package: 0603  Tolerance: ±1%  [R0603]
RL1  SRD-05VDC-SL-C  [Through Hole,15.6x19.2mm]
U2  3V_COIN_BATTERY_HOLDER  Battery Type: CR1220  [3V_COIN_BATERRY_HOLDER_CR1220]
U4  74HC595  [TSSOP16]
U5  TLP291  [SO-4]
X2  32.768kHz  [SMD3215-2P]

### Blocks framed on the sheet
HEADER: H1-H5 R23 R24

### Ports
SCL (bidir, see 4[4C], 5[3B], 5[6A]), SCL (bidir, see 4[4C], 5[3B], 5[8A]), SCL (bidir, see 4[4C], 5[6A], 5[8A]), SDA (bidir, see 4[4C], 5[3B], 5[6A]), SDA (bidir, see 4[4C], 5[3B], 5[8A]), SDA (bidir, see 4[4C], 5[6A], 5[8A])

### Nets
+3V3: H5.2
+5V: D5.1 H5.1 IC7.8(VCC) ICSP.6 Q5.3(C) Q6.3(C) Q7.3(C) Q8.3(C) R17.2 R18.2 R19.2 R21.2 R23.2 R24.2 RL1.5 U4.10(~{MR}) U4.16(VCC) U5.4(C)
GND: C31.2 C32.2 H3.4 H5.3 IC7.4(GND) ICSP.4 Q9.3(E) U2.2 U4.8(GND) U4.13(~{OE})
ADC0: H2.6 ; off-sheet ADC0
ADC1: H2.5 ; off-sheet ADC1
ADC2: H2.4 ; off-sheet ADC2
ADC3: H2.3 ; off-sheet ADC3
AREF: H3.3 ; off-sheet AREF
DIG1: H4.6 Q5.1(B) ; off-sheet DIG1
DIG2: H4.5 Q6.1(B) ; off-sheet DIG2
DIG3: H4.4 Q7.1(B) ; off-sheet DIG3
DIG4: H4.3 Q8.1(B) ; off-sheet DIG4
DS: H1.5 U4.14(DS) ; off-sheet DS
MISO: H1.2 ICSP.1 ; off-sheet MISO
MOSI: H1.3 ICSP.5 ; off-sheet MOSI
PD7: H4.1 ; off-sheet PD7
RELAY: H4.2 LED4.2 ; off-sheet RELAY
RESET: H5.4 ICSP.3 ; off-sheet RESET
RX: H4.7 ; off-sheet RX
SCK: H1.1 ICSP.2 ; off-sheet SCK
SH_CP: H1.4 U4.11(SH_CP) ; off-sheet SH_CP
ST_CP: H1.6 U4.12(ST_CP) ; off-sheet ST_CP
TX: H4.8 ; off-sheet TX
NetC31_1: C31.1 IC7.2(X2) X2.2
NetC32_1: C32.1 IC7.1(X1) X2.1
NetD5_2: D5.2 Q9.2(C) RL1.4
NetH2_1: H2.1 H3.1 IC7.6(SCL) R19.1 R23.1 ; port SCL
NetH2_2: H2.2 H3.2 IC7.5(SDA) R18.1 R24.1 ; port SDA
NetH6_1: H6.1 RL1.1
NetH6_2: H6.2 RL1.3
NetIC7_3: IC7.3(VBAT) U2.1
NetIC7_7: IC7.7(SQW) R17.1
NetJ1_1: J1.1 Q5.2(E)
NetJ1_2: J1.2 LED3.6(d4)
NetJ2_1: J2.1 Q6.2(E)
NetJ2_2: J2.2 LED3.8(d3)
NetJ3_1: J3.1 Q7.2(E)
NetJ3_2: J3.2 LED3.9(d2)
NetJ4_1: J4.1 Q8.2(E)
NetJ4_2: J4.2 LED3.12(d1)
NetJ5_1: J5.1 R22.2
NetJ5_2: J5.2 Q9.1(B)
NetLED3_1: LED3.1(e) R20.12
NetLED3_2: LED3.2(d) R20.13
NetLED3_3: LED3.3(p) R20.9
NetLED3_4: LED3.4(c) R20.14
NetLED3_5: LED3.5(g) R20.10
NetLED3_7: LED3.7(b) R20.15
NetLED3_10: LED3.10(f) R20.11
NetLED3_11: LED3.11(a) R20.16
NetLED4_1: LED4.1 U5.2(K)
NetR20_1: R20.1 U4.15(Q0)
NetR20_2: R20.2 U4.1(Q1)
NetR20_3: R20.3 U4.2(Q2)
NetR20_4: R20.4 U4.3(Q3)
NetR20_5: R20.5 U4.4(Q4)
NetR20_6: R20.6 U4.5(Q5)
NetR20_7: R20.7 U4.6(Q6)
NetR20_8: R20.8 U4.7(Q7)
NetR21_1: R21.1 U5.1(A)
NetR22_1: R22.1 U5.3(E)

Not connected (* = marked no-connect by the designer): J1 3*; J2 3*; J3 3*; J4 3*; J5 3*; RL1 2*; U4 9(Q7_S)*

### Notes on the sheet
- (near H1) PB0
- (near H1) PB1
- (near H1) PB2
- (near H1) PB3
- (near H1) PB4
- (near H1) PB5
- ADC4
- ADC5
- DS1307
- (near H4) PD4
- (near H4) PD5
- (near H4) PD6
- (near H4) PD0/RXD
- (near H4) PD1/TXD
- (near H4) PD2
- (near H4) PD3
- ICSP
- 4 DIGIT 7 SEGMENT
- CONTROL RELAY

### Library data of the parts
C31 C32 = C0603_MLCC_33pF_NP0_50V: as C25 on sheet MCU
D5 = 1N4007_M7: 1A 1V@1A 1kV SMA Diodes - General Purpose ROHS; Manufacturer: JSMSEMI; Mfr. Part: 1N4007 M7
H1 H2 = 6P 2.54mm Female Header: 2.54mm 1 6P Through Hole 1x6P Through Hole,P=2.54mm Female Headers ROHS; Manufacturer: BOOMELE(Boom Precision Elec); Mfr. Part: 2.54-1*6P
H3 H5 = 4P 2.54mm Female Header: 2.54mm 1 3A 4P Bronze -40℃~+105℃ Through Hole 1x4P Top Square Hole Through Hole,P=2.54mm Female Headers ROHS; Manufacturer: BOOMELE(Boom Precision Elec); Mfr. Part: 2.54-1*4P
H4 = 8P 2.54mm Female Header: 2.54mm 1 8P Through Hole 1x8P Through Hole,P=2.54mm Female Headers ROHS; Manufacturer: BOOMELE(Boom Precision Elec); Mfr. Part: 2.54-1*8P
H6 = KF301-5.0-2P: 1x2P -30℃~+120℃ 17A 250V Blue 14~22 Through Hole 5mm 1.5 1 2 Through Hole,P=5mm Screw Terminal Blocks ROHS; Manufacturer: Cixi Kefa Elec
IC7 = DS1307-SOIC8: I2C SOIC-8 Real Time Clocks ROHS; Manufacturer: MAXIM; Mfr. Part: DS1307Z+T&R; Key Attributes: 64 x 8, Serial, I²C Real-Time Clock
ICSP = 2x3P 2.54mm Female Header: 2.54mm 2.54mm 3A 2 6P -40℃~+105℃ Through Hole 2x3P Top Square Hole Through Hole,P=2.54mm Female Headers ROHS; Manufacturer: HanElectricity; Mfr. Part: 2541FV-2x3P
J1-J5 = JUMPER_SHUNT_3P: 250V 3A Through Hole Pin Header 2.5mm 3P 6mm -40℃~+105℃ 3mm 2.54mm 1 Black 1x3P Through Hole,P=2.54mm Pin Headers ROHS; Manufacturer: XFCN; Mfr. Part: PZ254V-11-03P
LED3 = LED7SEG_Common_Anode: Red 4 Common Anode 0.56 Through Hole LED Segment Displays ROHS; Manufacturer: ZHIHAO; Mfr. Part: FJ5461BH
LED4 = LED0603_Green: 2mA 20mcd~50mcd Water Clear 525nm -40℃~+85℃ Green 130° 75mW 2.65V 0603 LED Indication - Discrete ROHS; Manufacturer: Kingbright; Mfr. Part: KPT-1608LVZGCK; Key Attributes: 1.6X0.8mm SMD CHIP LED LAMP
Q5-Q8 = ZXTN2031FTA: 50V 200@2A,2V 1.2W 5A NPN SOT-23 Bipolar (BJT) ROHS; Manufacturer: DIODES; Transition frequency(fT): 125MHz
Q9 = 2N2222_SOT-89: 40V 500mW 600mA NPN SOT-89 Bipolar (BJT) ROHS; Manufacturer: CBI; Mfr. Part: 2N2222AU; Transition frequency(fT): 300MHz; Vce Saturation(VCE(sat)): 1V@500mA.50mA
R17-R19 R23 R24 = R0603_4.7kΩ_±1%: 100mW Thick Film Resistor 75V ±100ppm/℃ ±1% 4.7kΩ 0603 Chip Resistor - Surface Mount ROHS; Manufacturer: YAGEO; Mfr. Part: RC0603FR-074K7L
R20 = RES_ARRAY_8_RES_330Ω: 8 ±2% 330Ω 160mW ±100ppm/℃ SOIC-16-5.6mm Resistor Networks, Arrays ROHS; Manufacturer: BOURNS; Number of Resistors: 8
R21 = R0603_330Ω_±1%: as R16 on sheet MCU
R22 = R0603_2kΩ_±1%: as R6 on sheet VOLTAGE SOURCE
RL1 = SRD-05VDC-SL-C: 250V@AC 5V 15A 1 Form C: 1C (SPDT-CO) Through Hole,15.6x19.2mm Power Relays ROHS; Manufacturer: Songle Relay
U2 = 3V_COIN_BATTERY_HOLDER: Battery Holder -25℃~+85℃ Phosphor Bronze CR1220 SMD Button And Strip Battery Connector ROHS; Manufacturer: MYOUNG; Mfr. Part: BS-12-B3AA003
U4 = 74HC595: 8 2V~6V 1 Serial-to-Serial or Parallel TSSOP-16 Shift Registers ROHS; Manufacturer: Nexperia; Mfr. Part: 74HC595PW,118
U5 = TLP291: SO-4 Transistor, Photovoltaic Output Optoisolators ROHS; Manufacturer: TOSHIBA; Mfr. Part: TLP291(GB-TP,SE(T
X2 = Crystal_32.768Khz: 32.768kHz 12.5pF ±20ppm SMD3215-2P Crystals ROHS; Manufacturer: NDK; Mfr. Part: NX3215SA-32.768K-STD-MUA-8

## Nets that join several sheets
+3V3: VOLTAGE SOURCE (C18.2 C19.2 IC4.2 TP5.1), MCU (8 pins), Peripheral (H5.2)
+5V: VOLTAGE SOURCE (7 pins), MCU (14 pins), Peripheral (18 pins)
GND: VOLTAGE SOURCE (52 pins), MCU (14 pins), Peripheral (10 pins)
ADC0: MCU (U3.23), Peripheral (H2.6)
ADC1: MCU (U3.24), Peripheral (H2.5)
ADC2: MCU (U3.25), Peripheral (H2.4)
ADC3: MCU (U3.26), Peripheral (H2.3)
AREF: MCU (C29.2 U3.20), Peripheral (H3.3)
DATA+: VOLTAGE SOURCE (JP1.A6 JP1.B6), MCU (IC5.4)
DATA-: VOLTAGE SOURCE (JP1.A7 JP1.B7), MCU (IC5.5)
DIG1: MCU (U3.32), Peripheral (H4.6 Q5.1)
DIG2: MCU (U3.1), Peripheral (H4.5 Q6.1)
DIG3: MCU (U3.2), Peripheral (H4.4 Q7.1)
DIG4: MCU (U3.9), Peripheral (H4.3 Q8.1)
DS: MCU (U3.13), Peripheral (H1.5 U4.14)
MISO: MCU (U3.16), Peripheral (H1.2 ICSP.1)
MOSI: MCU (U3.15), Peripheral (H1.3 ICSP.5)
NetH2_1: MCU (U3.28), Peripheral (5 pins)
NetH2_2: MCU (U3.27), Peripheral (5 pins)
PD7: MCU (R16.1 U3.11), Peripheral (H4.1)
RELAY: MCU (U3.10), Peripheral (H4.2 LED4.2)
RESET: MCU (C30.1 R15.1 RESET.1 U3.29), Peripheral (H5.4 ICSP.3)
RX: MCU (R11.1 T1.3 U3.31), Peripheral (H4.7)
SCK: MCU (U3.17), Peripheral (H1.1 ICSP.2)
SH_CP: MCU (U3.14), Peripheral (H1.4 U4.11)
ST_CP: MCU (U3.12), Peripheral (H1.6 U4.12)
TX: MCU (R12.1 T2.3 U3.30), Peripheral (H4.8)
